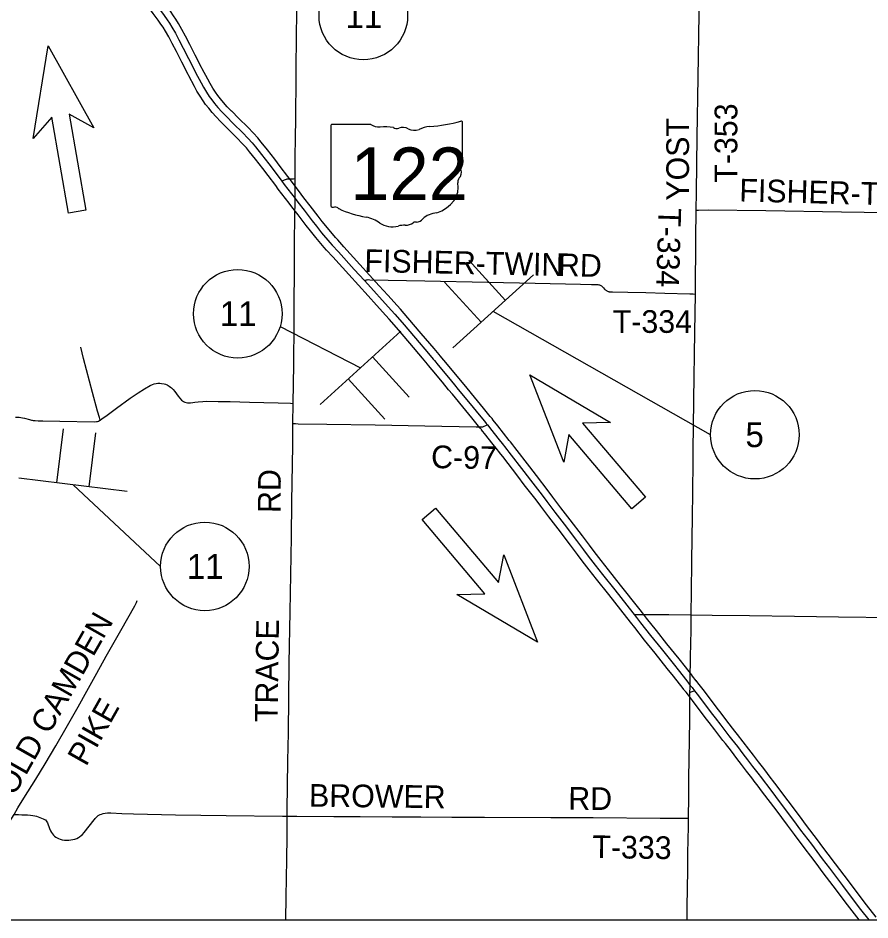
# Model space of a CAD drawing. Extents: x 1341221 to 1914484, y 79347 to 658398.
# Drawn here: x 1392220 to 1414179, y 580425 to 603681 of the extents above; entities that cross this region are included whole.
import ezdxf

# ---------------------------------------------------------------- set-up
doc = ezdxf.new("R2010")
doc.units = 0
for name, color, linetype in [('GM_X_Corporation_Text', 7, 'Continuous'), ('GM_X_County', 7, 'Continuous'), ('GM_X_County_Road_Text', 7, 'Continuous'), ('GM_X_Major_Lake_Text', 7, 'Continuous'), ('GM_X_Major_River', 7, 'Continuous'), ('GM_X_Major_River_Text', 7, 'Continuous'), ('GM_X_Minor_Lake_Text', 7, 'Continuous'), ('GM_X_Minor_River', 7, 'Continuous'), ('GM_X_State_Location', 7, 'Continuous'), ('GM_X_Township_Road_Text', 7, 'Continuous'), ('GM_X_Township_Text', 7, 'Continuous'), ('GM_X_US_Shield', 7, 'Continuous')]:
    doc.layers.add(name, color=color, linetype=linetype)

msp = doc.modelspace()

# ---------------------------------------------------------------- linework, layer by layer
at = {"layer": 'GM_X_Corporation_Text'}
for p, q in [((1401310, 600937), (1400316, 600937)), ((1403676, 599910), (1403676, 600988)), ((1400283, 600902), (1400283, 598841)), ((1403676, 599911), (1403676, 599910))]:
    msp.add_line(p, q, dxfattribs=at)
for centre, major_axis, start_param, end_param in [((1400322, 600906), (39.3, 0), 1.712693, 3.28349), ((1401547, 601176), (381, 0), 4.042523, 4.731795), ((1402467, 603746), (3599, 0), 4.814394, 5.042369), ((1403639, 600993), (37.8, 0), 6.141152, 7.989035), ((1401673, 599780), (1369, 0), 1.404758, 1.657858), ((1401984, 600917), (110, 0), 3.836095, 5.185415), ((1402145, 600679), (229, 0), 0.950623, 2.079405), ((1402441, 601005), (275, 0), 4.081561, 5.145723), ((1402926, 600308), (724, 0), 1.699011, 2.107814), ((1403667, 599831), (58.5, 0), 1.883978, 3.671073), ((1403296, 599695), (351, 0), 5.934695, 6.695948), ((1403636, 599906), (40.4, 0), 5.05454, 6.418171), ((1403812, 599459), (255, 0), 2.387724, 3.262537), ((1402669, 599322), (900, 0), 5.101752, 6.440018), ((1400322, 598837), (39.7, 0), 3.00124, 4.508301), ((1400328, 599047), (303, 0), 4.665946, 4.897461), ((1400390, 598722), (109, 0), 0.519207, 1.627899), ((1401768, 600574), (2599, 0), 4.195997, 4.488961), ((1403049, 598263), (493, 0), 1.647645, 2.488434), ((1400993, 597915), (813, 0), 0.823519, 1.323587), ((1401872, 598712), (516, 0), 4.026481, 4.996735), ((1402208, 598558), (275, 0), 4.691044, 5.507374), ((1402457, 598358), (77.4, 0), 1.147584, 2.315152), ((1402424, 598641), (291, 0), 4.937069, 5.64225), ((1402171, 598000), (424, 0), 1.495662, 1.94098)]:
    msp.add_ellipse(centre, major_axis=major_axis, ratio=0.8, start_param=start_param, end_param=end_param, dxfattribs=at)
at = {"layer": 'GM_X_County'}
msp.add_line((1410073, 592937), (1404469, 596118), dxfattribs=at)
for points in [[(1396950, 602405), (1396789, 602722), (1396650, 602997), (1396539, 603209), (1396446, 603383), (1396352, 603543), (1396285, 603651), (1396226, 603741), (1396147, 603855), (1396020, 604029), (1395924, 604154), (1395797, 604316), (1395655, 604497), (1395459, 604749), (1395299, 604957), (1395153, 605144), (1394989, 605356), (1394794, 605611), (1394677, 605758), (1394568, 605892)], [(1396603, 602228), (1396441, 602546), (1396303, 602819), (1396195, 603027), (1396106, 603192), (1396018, 603341), (1395957, 603441), (1395903, 603522), (1395829, 603629), (1395707, 603796), (1395616, 603915), (1395490, 604075), (1395347, 604257), (1395151, 604511), (1394991, 604718), (1394845, 604905), (1394680, 605118), (1394487, 605371), (1394372, 605514), (1394265, 605648)], [(1397722, 601282), (1397614, 601395), (1397520, 601500), (1397439, 601597), (1397369, 601687), (1397311, 601770), (1397241, 601876), (1397169, 601995), (1397109, 602101), (1396968, 602370), (1396950, 602405)], [(1397440, 601013), (1397327, 601131), (1397225, 601245), (1397135, 601353), (1397056, 601455), (1396989, 601549), (1396911, 601667), (1396832, 601799), (1396766, 601915), (1396622, 602191), (1396603, 602228)], [(1400465, 597958), (1400405, 598024), (1400196, 598268), (1400061, 598434), (1399953, 598572), (1399749, 598842), (1399587, 599049), (1399515, 599143), (1399240, 599506), (1399176, 599591), (1398981, 599855), (1398841, 600041), (1398649, 600285), (1398490, 600483), (1398398, 600590), (1398291, 600708), (1398141, 600863), (1397913, 601091), (1397719, 601285)], [(1400175, 597697), (1400112, 597767), (1399896, 598018), (1399756, 598191), (1399644, 598335), (1399439, 598605), (1399278, 598811), (1399205, 598907), (1398928, 599271), (1398863, 599359), (1398668, 599621), (1398531, 599803), (1398344, 600043), (1398190, 600234), (1398106, 600332), (1398006, 600441), (1397863, 600590), (1397637, 600815), (1397443, 601010)], [(1404215, 593623), (1404064, 593807), (1403718, 594228), (1403621, 594345), (1403463, 594539), (1403195, 594859), (1403101, 594972), (1403072, 595006), (1402945, 595159), (1402613, 595550), (1402267, 595954), (1402076, 596173), (1401989, 596270), (1401748, 596534), (1401532, 596778), (1401032, 597328), (1400622, 597784), (1400465, 597958)], [(1403913, 593376), (1403762, 593560), (1403417, 593979), (1403319, 594098), (1403162, 594291), (1402896, 594609), (1402802, 594722), (1402773, 594757), (1402647, 594908), (1402316, 595297), (1401972, 595700), (1401784, 595915), (1401700, 596008), (1401458, 596274), (1401242, 596518), (1400743, 597066), (1400332, 597523), (1400175, 597697)], [(1404470, 593310), (1404438, 593351), (1404393, 593406), (1404215, 593623)], [(1404165, 593068), (1404134, 593106), (1404091, 593160), (1403913, 593376)], [(1408252, 588422), (1408220, 588462), (1407752, 589055), (1407439, 589451), (1407251, 589692), (1407072, 589924), (1406950, 590087), (1406767, 590326), (1406451, 590744), (1406215, 591056), (1406005, 591330), (1405881, 591494), (1405580, 591883), (1405410, 592107), (1405023, 592611), (1404971, 592677), (1404911, 592753), (1404883, 592789), (1404736, 592973), (1404586, 593164), (1404470, 593310)], [(1407945, 588181), (1407914, 588221), (1407446, 588813), (1407133, 589210), (1406943, 589453), (1406762, 589688), (1406639, 589852), (1406456, 590090), (1406140, 590509), (1405905, 590819), (1405694, 591094), (1405571, 591257), (1405270, 591646), (1405100, 591871), (1404715, 592372), (1404665, 592436), (1404606, 592511), (1404578, 592545), (1404430, 592731), (1404280, 592922), (1404165, 593067)], [(1409701, 586594), (1409609, 586713), (1409576, 586755), (1409421, 586950), (1409258, 587156), (1408947, 587546), (1408676, 587886), (1408421, 588206), (1408315, 588341), (1408252, 588421)], [(1409391, 586357), (1409301, 586474), (1409271, 586513), (1409116, 586708), (1408953, 586913), (1408642, 587303), (1408370, 587643), (1408116, 587964), (1408008, 588100), (1407945, 588181)], [(1414339, 580499), (1414093, 580817), (1413853, 581132), (1413624, 581432), (1413289, 581874), (1413106, 582121), (1412966, 582305), (1412824, 582494), (1412547, 582862), (1412363, 583107), (1412071, 583496), (1411725, 583956), (1411582, 584145), (1411535, 584206), (1411442, 584329), (1411309, 584502), (1411177, 584674), (1411060, 584827), (1410914, 585015), (1410761, 585211), (1410698, 585291), (1410488, 585564), (1410341, 585757), (1410244, 585884), (1409911, 586322), (1409808, 586456), (1409746, 586537), (1409699, 586596)], [(1413903, 580425), (1413784, 580580), (1413543, 580895), (1413314, 581196), (1412977, 581640), (1412794, 581887), (1412655, 582070), (1412512, 582259), (1412235, 582627), (1412051, 582873), (1411759, 583261), (1411413, 583721), (1411271, 583910), (1411224, 583971), (1411132, 584092), (1411000, 584264), (1410868, 584437), (1410751, 584589), (1410607, 584775), (1410454, 584971), (1410390, 585052), (1410179, 585327), (1410031, 585520), (1409934, 585647), (1409601, 586086), (1409499, 586218), (1409438, 586297), (1409393, 586354)]]:
    msp.add_lwpolyline(points, dxfattribs=at)
for centre in [(1401121, 603745), (1397883, 596056), (1411213, 592937), (1397035, 589541)]:
    msp.add_circle(centre, 1141, dxfattribs=at)
at = {"layer": 'GM_X_County_Road_Text'}
for p, q in [((1398977, 595731), (1401044, 594662)), ((1393637, 591647), (1395895, 589541))]:
    msp.add_line(p, q, dxfattribs=at)
at = {"layer": 'GM_X_Minor_Lake_Text'}
msp.add_lwpolyline([(1435650, 641695), (1348099, 641695), (1348099, 580425), (1435650, 580425)], close=True, dxfattribs=at)
at = {"layer": 'GM_X_Minor_River'}
for p, q in [((1404781, 596401), (1403837, 597441)), ((1405509, 597061), (1403430, 595174)), ((1404157, 595835), (1403214, 596874)), ((1404469, 596118), (1404469, 596118)), ((1404469, 596118), (1404469, 596118)), ((1400005, 593719), (1402084, 595606)), ((1401356, 594945), (1402300, 593906)), ((1401044, 594662), (1401044, 594662)), ((1401044, 594662), (1401044, 594662)), ((1400732, 594379), (1401676, 593339)), ((1393219, 591698), (1393390, 593092)), ((1394055, 591595), (1394226, 592989)), ((1395031, 591475), (1392244, 591818)), ((1393637, 591647), (1393637, 591647)), ((1393637, 591647), (1393637, 591647))]:
    msp.add_line(p, q, dxfattribs=at)
at = {"layer": 'GM_X_State_Location'}
for points in [[(1394417, 605770), (1394524, 605636), (1394640, 605491), (1394835, 605237), (1394999, 605024), (1395145, 604838), (1395305, 604630), (1395501, 604377), (1395643, 604196), (1395770, 604035), (1395863, 603913), (1395988, 603742), (1396065, 603631), (1396121, 603546), (1396185, 603442), (1396276, 603287), (1396367, 603118), (1396476, 602908), (1396615, 602634), (1396777, 602316)], [(1396777, 602316), (1396795, 602280), (1396938, 602008), (1397000, 601897), (1397076, 601771), (1397150, 601659), (1397213, 601571), (1397287, 601475), (1397373, 601372), (1397471, 601263), (1397581, 601147)], [(1397581, 601147), (1397775, 600953), (1398002, 600727), (1398148, 600575), (1398252, 600461), (1398340, 600358), (1398496, 600164), (1398686, 599922), (1398825, 599738), (1399020, 599475), (1399084, 599389), (1399360, 599025), (1399433, 598930), (1399594, 598724), (1399799, 598453), (1399909, 598312), (1400046, 598143), (1400258, 597896), (1400320, 597827)], [(1400320, 597827), (1400477, 597653), (1400888, 597197), (1401147, 596911), (1401387, 596648), (1401603, 596404), (1401845, 596139), (1401930, 596044), (1402119, 595827), (1402464, 595424), (1402796, 595034), (1402923, 594882), (1402951, 594847), (1403046, 594734), (1403312, 594415), (1403470, 594222), (1403568, 594103), (1403913, 593684), (1404064, 593499)], [(1404064, 593499), (1404242, 593283), (1404286, 593228), (1404317, 593189)], [(1404317, 593189), (1404433, 593043), (1404583, 592852), (1404731, 592667), (1404759, 592632), (1404818, 592557), (1404869, 592491), (1405255, 591989), (1405425, 591765), (1405726, 591375), (1405850, 591212), (1406060, 590938), (1406295, 590627), (1406611, 590208), (1406794, 589969), (1406917, 589806), (1407097, 589572), (1407286, 589331), (1407599, 588934), (1408067, 588342), (1408098, 588301)], [(1408098, 588301), (1408162, 588221), (1408268, 588085), (1408523, 587764), (1408794, 587424), (1409106, 587035), (1409269, 586829), (1409423, 586634), (1409455, 586594), (1409546, 586475)], [(1409546, 586475), (1409592, 586417), (1409653, 586337), (1409756, 586204), (1410089, 585766), (1410186, 585639), (1410334, 585446), (1410544, 585172), (1410607, 585091), (1410761, 584895), (1410906, 584708), (1411022, 584556), (1411155, 584383), (1411287, 584211), (1411380, 584089), (1411426, 584027), (1411569, 583839), (1411915, 583379), (1412207, 582990), (1412391, 582744), (1412668, 582376), (1412811, 582187), (1412950, 582004), (1413133, 581757), (1413469, 581314), (1413698, 581014), (1413938, 580698), (1414149, 580425)]]:
    msp.add_lwpolyline(points, dxfattribs=at)
at = {"layer": 'GM_X_Township_Road_Text'}
for p, q in [((1392610, 600578), (1392997, 602962)), ((1392997, 602962), (1392997, 602962)), ((1392997, 602962), (1394170, 600851)), ((1394170, 600851), (1393536, 601203)), ((1393536, 601203), (1393968, 598731)), ((1393087, 601125), (1392610, 600578)), ((1393519, 598653), (1393087, 601125)), ((1393968, 598731), (1393519, 598653)), ((1393743, 598692), (1393743, 598692)), ((1405415, 594484), (1405415, 594484)), ((1405415, 594484), (1407495, 593255)), ((1406286, 592231), (1405415, 594484)), ((1407495, 593255), (1406769, 593239)), ((1406769, 593239), (1408392, 591324)), ((1406421, 592944), (1406286, 592231)), ((1408044, 591029), (1406421, 592944)), ((1408392, 591324), (1408044, 591029)), ((1408218, 591177), (1408218, 591177)), ((1402633, 590749), (1402981, 591044)), ((1402981, 591044), (1404603, 589129)), ((1404255, 588834), (1402633, 590749)), ((1402807, 590897), (1402807, 590897)), ((1404603, 589129), (1404738, 589842)), ((1404738, 589842), (1405609, 587589)), ((1403530, 588818), (1404255, 588834)), ((1405609, 587589), (1403530, 588818)), ((1405609, 587589), (1405609, 587589))]:
    msp.add_line(p, q, dxfattribs=at)
at = {"layer": 'GM_X_Township_Text'}
msp.add_line((1409626, 592586), (1409632, 593112), dxfattribs=at)
for points in [[(1409703, 598728), (1409708, 599187), (1409726, 600620), (1409751, 602148), (1409773, 603779), (1409776, 603976)], [(1409679, 596565), (1409680, 596616), (1409695, 597997), (1409703, 598728)], [(1409703, 598728), (1409758, 598728), (1410012, 598732), (1411492, 598715), (1413449, 598685), (1415776, 598652), (1417797, 598632), (1419153, 598617), (1419608, 598612), (1419651, 598611)], [(1401147, 596911), (1401168, 596919), (1401182, 596924), (1401203, 596930), (1401220, 596933), (1401245, 596935), (1401285, 596934), (1402704, 596902), (1404329, 596871), (1405550, 596845), (1406714, 596819), (1407004, 596812), (1407142, 596809), (1407164, 596808), (1407188, 596804), (1407209, 596798), (1407227, 596792), (1407245, 596784), (1407259, 596775), (1407275, 596760), (1407308, 596725), (1407334, 596694), (1407349, 596679), (1407361, 596670), (1407372, 596661), (1407387, 596653), (1407400, 596645), (1407414, 596638), (1407433, 596631), (1407448, 596626), (1407460, 596624), (1407471, 596623), (1407546, 596618), (1407937, 596613), (1408399, 596604), (1408896, 596588), (1409535, 596567), (1409625, 596566), (1409679, 596565)], [(1409632, 593112), (1409640, 593846), (1409665, 595580), (1409679, 596565)], [(1394340, 593316), (1394317, 593382), (1394267, 593547), (1394139, 594029), (1393908, 594898), (1393835, 595196)], [(1409546, 586475), (1409549, 586619), (1409557, 587212), (1409567, 587898), (1409572, 588235), (1409573, 588291), (1409583, 588915), (1409589, 589631), (1409596, 590311), (1409602, 590770), (1409622, 592215), (1409626, 592586)], [(1390400, 580425), (1390460, 580524), (1390780, 581041), (1390940, 581281), (1391227, 581742), (1391353, 581934), (1391548, 582239), (1391750, 582563), (1391996, 582952), (1392117, 583148), (1392216, 583316), (1392373, 583564), (1392682, 584057), (1392923, 584448), (1393198, 584911), (1393499, 585438), (1393767, 585919), (1393990, 586321), (1394248, 586787), (1394496, 587224), (1394866, 587888), (1395231, 588527), (1395270, 588607), (1395291, 588659)], [(1409466, 580425), (1409470, 580761), (1409482, 581708), (1409487, 582149), (1409498, 582834), (1409501, 583052), (1409501, 583077), (1409509, 583580), (1409514, 584075), (1409532, 585578), (1409540, 586286), (1409544, 586415), (1409546, 586475)], [(1409540, 586286), (1409571, 586305), (1409597, 586318), (1409624, 586327), (1409653, 586337)], [(1392117, 583148), (1392233, 583143), (1392320, 583140), (1392462, 583135), (1392541, 583129), (1392600, 583123), (1392651, 583114), (1392700, 583101), (1392871, 583035), (1392905, 583018), (1392928, 583003), (1392946, 582985), (1392964, 582959), (1392978, 582930), (1392996, 582881), (1393011, 582833), (1393032, 582780), (1393060, 582722), (1393085, 582677), (1393106, 582646), (1393131, 582616), (1393159, 582584), (1393192, 582561), (1393226, 582540), (1393261, 582523), (1393309, 582506), (1393360, 582493), (1393414, 582485), (1393467, 582481), (1393526, 582484), (1393582, 582490), (1393633, 582499), (1393682, 582511), (1393734, 582530), (1393775, 582551), (1393808, 582573), (1393845, 582601), (1393882, 582632), (1393924, 582678), (1394182, 583003), (1394192, 583017), (1394211, 583042), (1394232, 583066), (1394250, 583084), (1394265, 583100), (1394283, 583116), (1394307, 583131), (1394337, 583144), (1394369, 583155), (1394418, 583167), (1394468, 583177), (1394523, 583184), (1394612, 583185), (1394894, 583169), (1395193, 583159), (1396281, 583139), (1397586, 583122), (1399038, 583105), (1399160, 583104), (1399403, 583101), (1400363, 583096), (1401043, 583093), (1401860, 583086), (1402602, 583085), (1403402, 583077), (1404240, 583075), (1405954, 583069), (1407042, 583065), (1408774, 583046), (1409377, 583046), (1409448, 583049), (1409501, 583052)]]:
    msp.add_lwpolyline(points, dxfattribs=at)
at = {"layer": 'GM_X_US_Shield'}
msp.add_line((1399307, 593228), (1399315, 593746), dxfattribs=at)
for points in [[(1399379, 601167), (1399380, 601327), (1399386, 601916), (1399389, 602345), (1399392, 602671), (1399394, 602895), (1399396, 603247), (1399403, 603778), (1399405, 604137), (1399409, 604438), (1399414, 604770), (1399420, 605295), (1399425, 605628), (1399424, 605958)], [(1399315, 593746), (1399328, 594751), (1399338, 595794), (1399341, 596037), (1399344, 597437), (1399350, 597962), (1399360, 599025), (1399364, 599360), (1399362, 599539), (1399364, 599779), (1399365, 600086), (1399371, 600598), (1399377, 601077), (1399379, 601167)], [(1399020, 599475), (1399074, 599501), (1399092, 599510), (1399115, 599520), (1399136, 599527), (1399160, 599531), (1399180, 599533), (1399230, 599536), (1399318, 599538), (1399362, 599539)], [(1394180, 593273), (1394242, 593276), (1394257, 593277), (1394270, 593280), (1394293, 593289), (1394317, 593301), (1394340, 593316), (1394384, 593344), (1394514, 593443), (1394760, 593622), (1395113, 593881), (1395317, 594021), (1395479, 594120), (1395630, 594206), (1395689, 594235), (1395732, 594249), (1395779, 594259), (1395827, 594264), (1395875, 594264), (1395921, 594260), (1395986, 594250), (1396019, 594238), (1396067, 594219), (1396094, 594204), (1396119, 594188), (1396152, 594167), (1396174, 594148), (1396196, 594126), (1396219, 594104), (1396263, 594053), (1396305, 593994), (1396350, 593931), (1396391, 593878), (1396434, 593831), (1396457, 593810), (1396488, 593790), (1396523, 593776), (1396555, 593766), (1396587, 593762), (1396624, 593760), (1396664, 593763), (1396726, 593770), (1396777, 593779), (1396864, 593787), (1396981, 593795), (1397078, 593799), (1397375, 593797), (1397684, 593790), (1398183, 593774), (1398925, 593758), (1399244, 593748), (1399315, 593746)], [(1392151, 593389), (1392247, 593386), (1392292, 593381), (1392336, 593375), (1392385, 593363), (1392518, 593326), (1392563, 593314)], [(1392563, 593314), (1392582, 593309), (1392611, 593305), (1392662, 593301), (1392743, 593296), (1392856, 593292), (1393298, 593284), (1394180, 593273)], [(1399125, 580425), (1399134, 581018), (1399145, 581983), (1399154, 582578), (1399160, 583104), (1399161, 583244), (1399175, 584529), (1399188, 585251), (1399210, 587043), (1399236, 588372), (1399249, 589337), (1399268, 590293), (1399278, 591214), (1399299, 592647), (1399307, 593190), (1399307, 593228)], [(1399307, 593228), (1399372, 593224), (1399441, 593220), (1400183, 593210), (1401423, 593191), (1402708, 593168), (1404026, 593141), (1404161, 593138), (1404184, 593140), (1404200, 593142), (1404219, 593148), (1404297, 593180), (1404317, 593189)], [(1404317, 593189), (1404433, 593043), (1404583, 592852), (1404731, 592667), (1404759, 592632), (1404818, 592557), (1404869, 592491), (1405255, 591989), (1405425, 591765), (1405726, 591375), (1405850, 591212), (1406060, 590938), (1406295, 590627), (1406611, 590208), (1406794, 589969), (1406917, 589806), (1407097, 589572), (1407286, 589331), (1407599, 588934), (1408067, 588342), (1408098, 588301)], [(1408098, 588301), (1408210, 588301), (1408997, 588298), (1409573, 588291)], [(1409573, 588291), (1410116, 588284), (1411076, 588272), (1412233, 588255), (1413372, 588243), (1414785, 588228), (1415917, 588216), (1417120, 588201), (1418303, 588191), (1419526, 588176), (1420613, 588163), (1423504, 588136), (1424514, 588123), (1425772, 588109), (1426271, 588096), (1427353, 588073), (1427473, 588071), (1429135, 588036), (1430273, 588010), (1433029, 587954), (1435053, 587907), (1435153, 587905), (1435650, 587892)]]:
    msp.add_lwpolyline(points, dxfattribs=at)

# ---------------------------------------------------------------- texts
at = {"layer": 'GM_X_Corporation_Text'}
msp.add_text('122', height=1357.4, dxfattribs=at).set_placement((1400787, 598986))
at = {"layer": 'GM_X_County'}
for s, height, p in [('11', 638.8, (1400657, 603425)), ('11', 638.8, (1397419, 595737)), ('5', 639, (1410969, 592617)), ('11', 638.8, (1396571, 589221))]:
    msp.add_text(s, height=height, dxfattribs=at).set_placement(p)
at = {"layer": 'GM_X_Major_Lake_Text'}
for s, rotation, p in [('C-97', 358.9714, (1402863, 592078)), ('RD', 89.5059, (1398987, 590917)), ('TRACE', 89.1903, (1398910, 585522))]:
    msp.add_text(s, height=585, rotation=rotation, dxfattribs=at).set_placement(p)
at = {"layer": 'GM_X_Major_River'}
for s in ['s', 'r']:
    msp.add_text(s, height=1.95, dxfattribs=at).set_placement((1397812, 600326))
msp.add_text('122', height=1.95, rotation=0, dxfattribs=at).set_placement((1397124, 600184))
at = {"layer": 'GM_X_Major_River_Text'}
for s, rotation, p in [('T-353', 90, (1410760, 599435)), ('YOST', 90, (1409515, 598972)), ('FISHER-TWIN', 358.4926, (1410806, 598953)), ('T-334', 268.3151, (1408730, 598787)), ('FISHER-TWIN', 358.8157, (1401144, 597134)), ('RD', 358.5119, (1406130, 597031)), ('T-334', 0, (1407549, 595563)), ('OLD CAMDEN', 60.4221, (1392119, 583598)), ('PIKE', 60.5241, (1393975, 584363)), ('BROWER', 359.356, (1399718, 583346)), ('RD', 359.5064, (1406401, 583269)), ('T-333', 359.1579, (1407019, 582023))]:
    msp.add_text(s, height=585, rotation=rotation, dxfattribs=at).set_placement(p)

doc.saveas('drawing.dxf')
